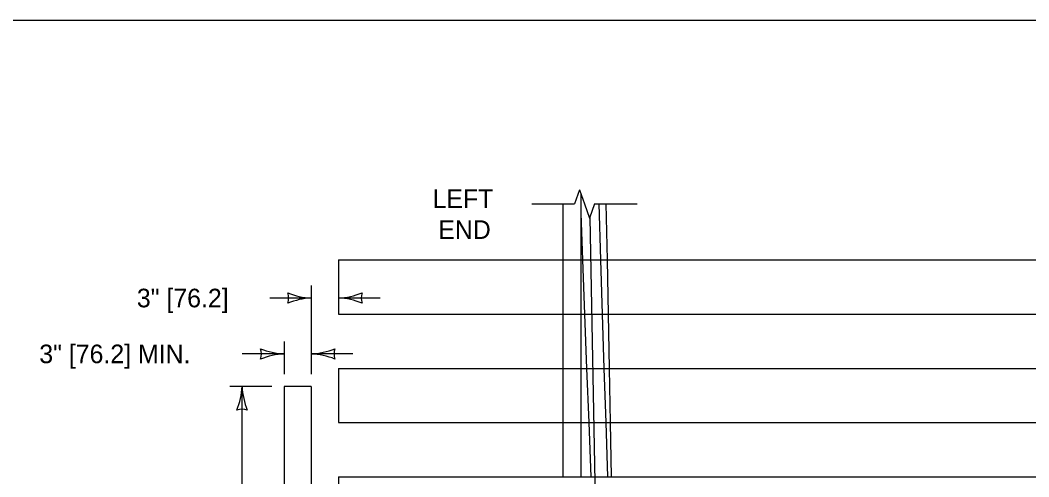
# Model space of a CAD drawing. Extents: x 49991.4 to 50021, y 49987.6 to 50011.4.
# Drawn here: x 50008.155 to 50011.41, y 49997.525 to 49998.999 of the extents above; entities that cross this region are included whole.
import ezdxf

# ---------------------------------------------------------------- set-up
doc = ezdxf.new("R2010")
doc.units = 0
for name, color, linetype in [('Level 1', 7, 'Continuous'), ('Level 2', 7, 'Continuous'), ('Level 3', 7, 'Continuous'), ('Level 4', 7, 'Continuous'), ('Level 6', 7, 'Continuous')]:
    doc.layers.add(name, color=color, linetype=linetype)

msp = doc.modelspace()

# ---------------------------------------------------------------- linework, layer by layer
at = {"layer": 'Level 1'}
for p, q in [((50009.9652, 49998.2253), (50009.9652, 49998.4389)), ((50009.9068, 49998.4062), (50009.9068, 49998.2253)), ((50010.0225, 49998.4062), (50010.0282, 49998.2253)), ((50010.0503, 49998.2253), (50010.0468, 49998.4062)), ((50009.9707, 49998.2253), (50009.9652, 49998.3768)), ((50009.1825, 49998.2253), (50009.1825, 49998.0503)), ((50009.1825, 49998.2253), (50012.6915, 49998.2253)), ((50009.1825, 49998.0503), (50012.9415, 49998.0503)), ((50009.9068, 49998.0503), (50009.9068, 49997.8753)), ((50009.9652, 49997.8753), (50009.9652, 49998.0503)), ((50009.9841, 49997.8753), (50009.9774, 49998.0503)), ((50010.0337, 49998.0503), (50010.0393, 49997.8753)), ((50010.0568, 49997.8753), (50010.0536, 49998.0503)), ((50009.1825, 49997.8753), (50009.1825, 49997.7003)), ((50009.1825, 49997.8753), (50013.1914, 49997.8753)), ((50009.0948, 49997.8169), (50009.0073, 49997.8169)), ((50009.0073, 49997.8169), (50009.0073, 49995.5419)), ((50009.0948, 49997.8169), (50009.0948, 49995.5419)), ((50009.1825, 49997.7003), (50013.4413, 49997.7003)), ((50009.9068, 49997.7003), (50009.9068, 49997.5253)), ((50009.9652, 49997.5253), (50009.9652, 49997.7003)), ((50009.9978, 49997.5253), (50009.9911, 49997.7003)), ((50010.0451, 49997.7003), (50010.0506, 49997.5253)), ((50010.0635, 49997.5253), (50010.0603, 49997.7003)), ((50009.1825, 49997.5253), (50009.1825, 49997.3503)), ((50009.1825, 49997.5253), (50013.6912, 49997.5253))]:
    msp.add_line(p, q, dxfattribs=at)
msp.add_lwpolyline([(49999.3835, 49998.9992), (50016.7501, 49998.9992), (50016.7501, 49987.7988), (49999.3835, 49987.7988)], close=True, dxfattribs=at)
at = {"layer": 'Level 3'}
for p, q in [((50009.0948, 49998.1424), (50009.0948, 49997.8569)), ((50009.0948, 49998.1024), (50008.9605, 49998.1024)), ((50009.3168, 49998.1024), (50009.1825, 49998.1024)), ((50009.0073, 49997.9621), (50009.0073, 49997.8569)), ((50009.0073, 49997.9221), (50008.8714, 49997.9221)), ((50009.2291, 49997.9221), (50009.0948, 49997.9221)), ((50008.9673, 49997.8169), (50008.8314, 49997.8169)), ((50008.8714, 49996.5919), (50008.8714, 49997.8169))]:
    msp.add_line(p, q, dxfattribs=at)
for centre, radius, start, end in [((50009.104, 49998.3245), 0.2223, 247.456, 267.6395), ((50008.9666, 49998.1024), 0.0548, 342.1388, 17.8612), ((50009.1063, 49997.8697), 0.233, 92.8273, 112.0772), ((50009.171, 49998.3351), 0.233, 272.8273, 292.0772), ((50009.1733, 49997.8803), 0.2223, 67.456, 87.6395), ((50009.3107, 49998.1024), 0.0548, 162.1388, 197.8612), ((50009.0165, 49998.1442), 0.2223, 247.456, 267.6395), ((50008.8791, 49997.9221), 0.0548, 342.1388, 17.8612), ((50009.0833, 49998.1548), 0.233, 272.8273, 292.0772), ((50009.223, 49997.9221), 0.0548, 162.1388, 197.8612), ((50009.0188, 49997.6894), 0.233, 92.8273, 112.0772), ((50009.0856, 49997.7), 0.2223, 67.456, 87.6395), ((50008.6493, 49997.8261), 0.2223, 337.456, 357.6395), ((50009.1041, 49997.8284), 0.233, 182.8273, 202.0772), ((50008.8714, 49997.6887), 0.0548, 72.1388, 107.8612)]:
    msp.add_arc(centre, radius, start, end, dxfattribs=at)
at = {"layer": 'Level 4'}
for p, q in [((50009.9935, 49998.362), (50010.0235, 49996.7669)), ((50009.9068, 49998.2253), (50009.9068, 49998.0503)), ((50009.9652, 49998.0503), (50009.9652, 49998.2253)), ((50009.9774, 49998.0503), (50009.9707, 49998.2253)), ((50010.0282, 49998.2253), (50010.0337, 49998.0503)), ((50010.0536, 49998.0503), (50010.0503, 49998.2253)), ((50009.9068, 49997.8753), (50009.9068, 49997.7003)), ((50009.9652, 49997.7003), (50009.9652, 49997.8753)), ((50009.9911, 49997.7003), (50009.9841, 49997.8753)), ((50010.0393, 49997.8753), (50010.0451, 49997.7003)), ((50010.0603, 49997.7003), (50010.0568, 49997.8753))]:
    msp.add_line(p, q, dxfattribs=at)
at = {"layer": 'Level 6'}
for p, q in [((50009.9606, 49998.4519), (50009.9444, 49998.4062)), ((50009.9606, 49998.4519), (50009.9768, 49998.4062)), ((50009.8068, 49998.4062), (50009.9444, 49998.4062)), ((50009.9768, 49998.4062), (50009.993, 49998.3605)), ((50010.0092, 49998.4062), (50009.993, 49998.3605)), ((50010.0092, 49998.4062), (50010.1468, 49998.4062))]:
    msp.add_line(p, q, dxfattribs=at)

# ---------------------------------------------------------------- texts
at = {"layer": 'Level 2'}
for s, p in [('LEFT', (50009.4861, 49998.3932)), ('END', (50009.5046, 49998.2932)), ('3" [76.2]', (50008.5319, 49998.0724)), ('3" [76.2] MIN.', (50008.217, 49997.8921))]:
    msp.add_text(s, height=0.06, dxfattribs=at).set_placement(p)

doc.saveas('drawing.dxf')
